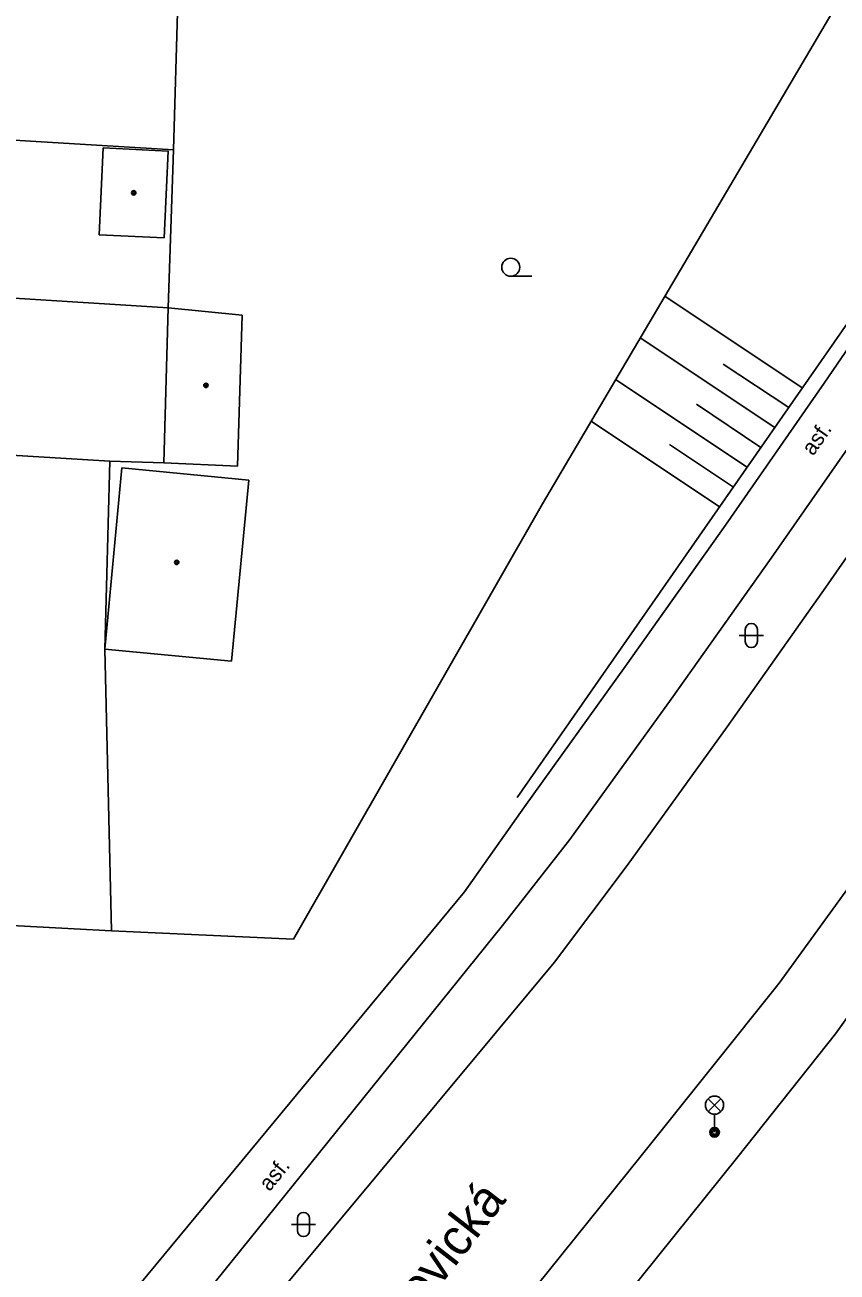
# Model space of a CAD drawing. Extents: x -596024 to -594475, y -1163820 to -1161957.
# Drawn here: x -595752.9 to -595719.3, y -1163071.7 to -1163020 of the extents above; entities that cross this region are included whole.
import ezdxf

# ---------------------------------------------------------------- set-up
doc = ezdxf.new("R2010")
doc.units = 0
for name, color, linetype in [('Level 10', 7, 'Continuous'), ('Level 11', 7, 'Continuous'), ('Level 14', 7, 'Continuous'), ('Level 15', 7, 'Continuous'), ('Level 33', 7, 'Continuous'), ('Level 36', 7, 'Continuous'), ('Level 39', 7, 'Continuous'), ('Level 40', 7, 'Continuous'), ('Level 49', 7, 'Continuous'), ('Level 5', 7, 'Continuous'), ('Level 7', 7, 'Continuous')]:
    doc.layers.add(name, color=color, linetype=linetype)

msp = doc.modelspace()

# ---------------------------------------------------------------- linework, layer by layer
at = {"layer": 'Level 10'}
for points in [[(-595721.7, -1163059.71), (-595717.48, -1163053.88), (-595713.31, -1163048.02), (-595709.2, -1163042.12), (-595705.13, -1163036.19), (-595701.11, -1163030.22), (-595697.15, -1163024.22), (-595693.24, -1163018.19), (-595689.38, -1163012.12), (-595685.57, -1163006.01), (-595681.81, -1162999.88), (-595678.2, -1162993.94), (-595674.63, -1162987.98), (-595671.1, -1162981.99), (-595667.61, -1162975.97), (-595664.16, -1162969.94), (-595660.76, -1162963.87), (-595654.08, -1162951.68), (-595650.81, -1162945.55), (-595647.58, -1162939.39), (-595641.51, -1162927.59)], [(-595651.4, -1162929.55), (-595654.48, -1162935.46), (-595657.71, -1162941.62), (-595660.99, -1162947.76), (-595664.31, -1162953.87), (-595667.67, -1162959.97), (-595671.08, -1162966.03), (-595674.53, -1162972.07), (-595678.02, -1162978.09), (-595685.14, -1162990.05), (-595688.76, -1162995.99), (-595692.47, -1163002.01), (-595696.23, -1163008.01), (-595700.03, -1163013.97), (-595703.88, -1163019.9), (-595707.78, -1163025.81), (-595711.73, -1163031.68), (-595715.73, -1163037.51), (-595719.77, -1163043.32), (-595723.86, -1163049.09), (-595727.99, -1163054.83)], [(-595707.02, -1163044.27), (-595710.68, -1163049.56), (-595715.63, -1163056.57), (-595719.38, -1163061.8)], [(-595727.99, -1163054.83), (-595731, -1163058.84)], [(-595731, -1163058.84), (-595757.62, -1163090.81), (-595776.56, -1163111.46), (-595794.79, -1163128.1), (-595813.08, -1163143.28), (-595835.32, -1163158.28), (-595856.17, -1163170.04), (-595881.68, -1163181.85), (-595895.55, -1163187.5), (-595919.36, -1163195.51)], [(-595721.7, -1163059.71), (-595727.41, -1163066.85), (-595752.54, -1163098.12), (-595783.15, -1163128.73), (-595808.42, -1163149.56), (-595821.75, -1163159.21), (-595852.05, -1163176.84), (-595874.52, -1163187.57), (-595889.03, -1163193.54), (-595907.96, -1163200.7)], [(-595851.62, -1163180.03), (-595852, -1163179.28), (-595851.17, -1163178.78), (-595850.24, -1163179.43), (-595816.94, -1163159.5), (-595817.13, -1163159.29), (-595816.41, -1163158.71), (-595816.25, -1163159.04), (-595807.1, -1163152.51), (-595807.94, -1163151.43), (-595807.25, -1163150.95), (-595805.84, -1163151.47), (-595780.97, -1163130.98), (-595770.46, -1163121), (-595771.09, -1163120.34), (-595770.47, -1163119.85), (-595769.45, -1163120.04), (-595749.44, -1163099.31), (-595723.41, -1163066.9), (-595719.38, -1163061.8)]]:
    msp.add_lwpolyline(points, dxfattribs=at)
at = {"layer": 'Level 11'}
for points in [[(-595732.24, -1163052.41), (-595728.06, -1163046.59), (-595723.93, -1163040.75), (-595719.84, -1163034.87), (-595715.8, -1163028.96), (-595707.84, -1163017.05), (-595703.93, -1163011.06), (-595700.07, -1163005.03), (-595696.25, -1162998.97), (-595692.47, -1162992.89), (-595688.94, -1162987.06), (-595685.45, -1162981.21), (-595678.58, -1162969.44), (-595675.2, -1162963.52), (-595671.86, -1162957.58), (-595668.56, -1162951.61), (-595665.3, -1162945.63), (-595662.07, -1162939.63), (-595658.89, -1162933.6), (-595655.83, -1162927.6)], [(-595653.73, -1162928.39), (-595656.76, -1162934.35), (-595659.94, -1162940.45), (-595663.16, -1162946.53), (-595666.43, -1162952.58), (-595669.74, -1162958.61), (-595673.1, -1162964.62), (-595676.51, -1162970.59), (-595679.96, -1162976.55), (-595686.99, -1162988.37), (-595690.58, -1162994.24), (-595698.16, -1163006.39), (-595702.03, -1163012.42), (-595705.93, -1163018.42), (-595709.89, -1163024.39), (-595713.89, -1163030.33), (-595717.94, -1163036.23), (-595722.03, -1163042.11), (-595726.17, -1163047.95), (-595730.36, -1163053.76)], [(-595746.59, -1163019.06), (-595746.77, -1163025.21)], [(-595765.65, -1163024.06), (-595746.77, -1163025.21)], [(-595746.77, -1163025.21), (-595746.98, -1163031.75)], [(-595746.98, -1163031.75), (-595761.27, -1163030.85), (-595763.79, -1163030.69), (-595766.55, -1163030.52)], [(-595764.57, -1163037.17), (-595749.4, -1163038.1)], [(-595749.6, -1163045.88), (-595749.4, -1163038.1)], [(-595749.4, -1163038.1), (-595747.16, -1163038.16)], [(-595749.33, -1163057.54), (-595749.6, -1163045.88)], [(-595734.72, -1163055.92), (-595732.24, -1163052.41)], [(-595733.15, -1163057.32), (-595730.36, -1163053.76)], [(-595748.82, -1163072.97), (-595734.72, -1163055.92)], [(-595733.15, -1163057.32), (-595759.5, -1163089.99), (-595778.37, -1163109.17), (-595795.84, -1163125.04), (-595814.68, -1163140.46), (-595836.38, -1163155.41), (-595857.69, -1163167.34), (-595883.05, -1163179.29), (-595896.6, -1163185.46), (-595919.59, -1163194.75), (-595919.36, -1163195.51)]]:
    msp.add_lwpolyline(points, dxfattribs=at)
at = {"layer": 'Level 14'}
msp.add_lwpolyline([(-595711.35, -1163021.57), (-595732.55, -1163052.02)], dxfattribs=at)
at = {"layer": 'Level 15'}
for points in [[(-595726.43, -1163031.27), (-595720.75, -1163035.06)], [(-595727.45, -1163032.99), (-595721.89, -1163036.71)], [(-595724.02, -1163034.08), (-595721.31, -1163035.88)], [(-595728.47, -1163034.72), (-595723.03, -1163038.35)], [(-595725.13, -1163035.74), (-595722.46, -1163037.53)], [(-595729.49, -1163036.44), (-595724.17, -1163039.99)], [(-595726.24, -1163037.41), (-595723.6, -1163039.17)]]:
    msp.add_lwpolyline(points, dxfattribs=at)
at = {"layer": 'Level 33'}
for p, q in [((-595724.645, -1163065.02), (-595724.115, -1163064.49)), ((-595724.645, -1163064.49), (-595724.115, -1163065.02)), ((-595724.38, -1163065.13), (-595724.38, -1163065.88))]:
    msp.add_line(p, q, dxfattribs=at)
for centre, radius in [((-595724.38, -1163064.755), 0.375), ((-595724.38, -1163065.88), 0.2), ((-595724.38, -1163065.88), 0.145), ((-595724.38, -1163065.88), 0.0876)]:
    msp.add_circle(centre, radius, dxfattribs=at)
at = {"layer": 'Level 36'}
for p, q in [((-595732.81, -1163030.445), (-595731.935, -1163030.445)), ((-595723.356, -1163045.316), (-595722.356, -1163045.316)), ((-595723.106, -1163045.066), (-595723.106, -1163045.566)), ((-595722.606, -1163045.066), (-595722.606, -1163045.566)), ((-595741.636, -1163069.446), (-595741.636, -1163069.946)), ((-595741.136, -1163069.446), (-595741.136, -1163069.946)), ((-595741.886, -1163069.696), (-595740.886, -1163069.696))]:
    msp.add_line(p, q, dxfattribs=at)
msp.add_circle((-595732.81, -1163030.07), 0.375, dxfattribs=at)
for centre, start, end in [((-595722.856, -1163045.066), 0, 180), ((-595722.856, -1163045.566), 180, 0), ((-595741.386, -1163069.446), 0, 180), ((-595741.386, -1163069.946), 180, 0)]:
    msp.add_arc(centre, 0.25, start, end, dxfattribs=at)
at = {"layer": 'Level 39'}
for centre, radius in [((-595748.41, -1163026.99), 0.09), ((-595748.41, -1163026.99), 0.0398), ((-595745.42, -1163034.96), 0.09), ((-595745.42, -1163034.96), 0.0398), ((-595746.63, -1163042.29), 0.09), ((-595746.63, -1163042.29), 0.0398)]:
    msp.add_circle(centre, radius, dxfattribs=at)
at = {"layer": 'Level 5'}
for points in [[(-595749.84, -1163028.73), (-595749.68, -1163025.13)], [(-595749.68, -1163025.13), (-595746.98, -1163025.26)], [(-595746.98, -1163025.26), (-595747.15, -1163028.85)], [(-595747.15, -1163028.85), (-595749.84, -1163028.73)], [(-595747.16, -1163038.16), (-595746.98, -1163031.75)], [(-595746.98, -1163031.75), (-595743.92, -1163032.05)], [(-595743.92, -1163032.05), (-595744.11, -1163038.3)], [(-595744.11, -1163038.3), (-595747.16, -1163038.16)], [(-595749.6, -1163045.88), (-595748.9, -1163038.37)], [(-595748.9, -1163038.37), (-595743.65, -1163038.88)], [(-595743.65, -1163038.88), (-595744.36, -1163046.38)], [(-595744.36, -1163046.38), (-595749.6, -1163045.88)]]:
    msp.add_lwpolyline(points, dxfattribs=at)
at = {"layer": 'Level 7'}
for points in [[(-595746.59, -1163019.06), (-595746.58, -1163018.47), (-595719.49, -1163019.48), (-595731.5, -1163039.86), (-595741.8, -1163057.88), (-595749.33, -1163057.54)], [(-595749.33, -1163057.54), (-595765.3, -1163056.68), (-595764.57, -1163037.17)]]:
    msp.add_lwpolyline(points, dxfattribs=at)

# ---------------------------------------------------------------- texts
at = {"layer": 'Level 40'}
for rotation, p in [(54.87, (-595720.3, -1163037.91)), (50.75, (-595742.79, -1163068.36))]:
    msp.add_text('asf.', height=0.65, rotation=rotation, dxfattribs=at).set_placement(p)
at = {"layer": 'Level 49'}
msp.add_text('Černovická', height=1.5, rotation=52.19, dxfattribs=at).set_placement((-595739.11, -1163076.61))

doc.saveas('drawing.dxf')
